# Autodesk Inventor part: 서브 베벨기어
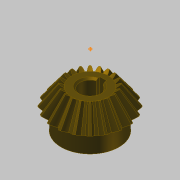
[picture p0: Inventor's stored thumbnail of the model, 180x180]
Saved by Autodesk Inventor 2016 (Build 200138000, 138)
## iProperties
Created: 2014-10
Part Number: 서브 베벨기어
Material: 강철, 탄소
Document SubType Name: Modeling
Designer: KYOUNG IL JANG
Categories: <?xml version="1.0" encoding="UTF-16"?> <MemberInstance><Categories><FamilyTemplate><FamilyTemplateParameter ValueType="xs:double" Id="1" ObjectReferenceKey="da
Mass: 135.037 g
Surface Area: 63.6518 cm^2
Volume: 17.1585 cm^3
Density: 7.87 g/cm^3
Appearance: 얼룩무늬
CustomPartVersion: 1
Revision Number: 1
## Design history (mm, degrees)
node "맨 위 점"
node "메쉬 평면2"
sketch "톱니 본체 스케치"
  geometry: L1 (0, 0)-(18.003, -31.331); L2 (18.003, -31.331)-(21.664, -28.891); L3 (21.664, -28.891)-(0, 0); L4 (20, -30)-(0, 0); L5 (10.813, -18.818)-(13.012, -17.352); L6 (18.003, -31.331)-(10.813, -18.818); L7 (21.664, -28.891)-(13.012, -17.352); L8 (0, -39.387)-(0, 6.564) reference; L9 (0, -30)-(21.664, -30)
  constraints: 16 end point, 4 point on line, 3 perpendicular, 2 collinear, 1 horizontal alignment, 1 vertical alignment
  dimensions: "d0" = 40 diameter of L4.start L8 (= da_de); "d1" = 36.00616 diameter of L1.end L8 (= da_dfe); "d2" = 43.3282 diameter of L2.end L8 (= da_dae); "d3" = 14.4 distance between parallel lines of L2 L5 (= da_b); "d4" = 28.8906 vertical distance of L2.end L1.start (= da_ve)
revolve "톱니 본체" sketch "톱니 본체 스케치" stored, may be unused: angle "d5" = 90 deg
node "시작점"
node "톱니 평면"
sketch "시작 스케치"
  geometry: L1 (0, -23.505)-(0, 10.645) reference; L2 (-0.834, -2.928)-(0.834, -2.928); A1 r 8.898 centre (-9.698, -3.713) between (-0.834, -2.928) and (-3.903, 3.04); A2 r 8.898 centre (9.698, -3.713) between (3.903, 3.04) and (0.834, -2.928); A3 r 27.357 centre (0, -24.037) between (3.903, 3.04) and (-3.903, 3.04); 1 further point
  constraints: 6 point on circle, 3 centre point, 3 symmetric about line, 2 end point, 1 coincident, 1 perpendicular, 1 other
  dimensions: "d7" = 8.89846 radius of A1 (= fd_rr); "d8" = 9.69794 horizontal distance of point (0, -24.037) A1.centre (= fd_x); "d9" = 20.32439 vertical distance of point (0, -24.037) A1.centre (= fd_y); "d57" = 27.35701 radius of A3 (= 0.5 x fd_dva + 0.3 x da_he); "d58" = 21.10901 distance from line of A3.centre L2 (= 0.5 x fd_dva - 1.12 x da_he)
node "끝점"
  node "끝 평면"
sketch "3D 스케치 오른쪽"
  node "Helical Curve Right" dims "d65" = 229.90621 (computed from da_dm, da_delta, da_beta), "d66" = 31.5, "d67" = 40 (= da_de), "d68" = -5.88003 (= -da_delta), "d69" = 12.16458 (computed from fd_loft, da_delta)
node "끝 평면 오른쪽"
sketch "끝 스케치 오른쪽"
  geometry: L1 (0, -22.649)-(0, 12.15) reference; L2 (-0.497, -1.72)-(0.497, -1.72); A1 r 5.299 centre (-5.775, -2.187) between (-0.497, -1.72) and (-2.324, 1.834); A2 r 5.299 centre (5.775, -2.187) between (2.324, 1.834) and (0.497, -1.72); A3 r 16.291 centre (0, -14.29) between (2.324, 1.834) and (-2.324, 1.834); 1 further point
  constraints: 6 point on circle, 3 centre point, 3 symmetric about line, 2 end point, 1 coincident, 1 perpendicular, 1 other
  dimensions: "d70" = 5.77526 horizontal distance of A3.centre A1.centre (computed from fd_x, fd_ratio); "d71" = 12.10346 vertical distance of point (0, -14.29) A1.centre (computed from fd_y, fd_ratio); "d72" = 5.29916 radius of A1 (computed from fd_rr, fd_ratio); "d73" = 12.57071 distance from line of point (0, -14.29) L2 (computed from d58, fd_ratio); "d74" = 16.29149 radius of A3 (computed from d57, fd_ratio)
feature "로프트 오른쪽" sketch "끝 스케치 오른쪽" dims "d75" = 0, "d77" = 0, "d79" = 0, "d80" = 90 deg, "d85" = 20, "d92" = 90 deg, "d93" = 90 deg, "da_teethtype" = 0 [user parameter]
sketch "3D 스케치 왼쪽"
  node "Helical Curve Left" dims "d26" = 229.90621 (computed from da_dm, da_delta, da_beta), "d27" = 12.16458 (computed from fd_loft, da_delta), "d28" = 40 (= da_de), "d29" = -5.88003 (= -da_delta)
node "끝 평면 왼쪽"
sketch "끝 스케치 왼쪽" dims "d56" = 10.82768 (derived)
  geometry: L1 (0, -35.087)-(0, 18.089) reference; L2 (-0.497, -1.716)-(0.497, -1.716); A1 r 5.299 centre (-5.775, -2.183) between (-0.497, -1.716) and (-2.324, 1.838); A2 r 5.299 centre (5.775, -2.183) between (2.324, 1.838) and (0.497, -1.716); A3 r 16.291 centre (0, -14.287) between (2.324, 1.838) and (-2.324, 1.838); 2 further points; 1 other entity
  constraints: 6 point on circle, 3 centre point, 3 symmetric about line, 2 end point, 1 coincident, 2 other
  dimensions: "d30" = 5.29916 radius of A1 (computed from fd_rr, fd_ratio); "d31" = 5.77526 horizontal distance of point (0, -14.287) A1.centre (computed from fd_x, fd_ratio); "d32" = 12.10346 vertical distance of A1.centre point (0, -14.287) (computed from fd_y, fd_ratio); "d61" = 16.29149 radius of A3 (computed from d57, fd_ratio); "d62" = 12.57071 distance from line of point (0, -14.287) L2 (computed from d58, fd_ratio)
feature "로프트 왼쪽" sketch "끝 스케치 왼쪽" dims "d35" = 0, "d37" = 0, "d39" = 0, "d40" = 90 deg, "d84" = 10, "d90" = 90 deg, "d91" = 90 deg, "da_teethtype" = 0 [user parameter]
sketch "본체 스케치"
  geometry: L1 (0, -35.038)-(0, -19.531) reference; L2 (18.003, -31.331)-(10.813, -18.818) reference; L3 (10.813, -18.818)-(0, -18.818); L4 (18.003, -31.331)-(0, -31.331)
  constraints: 4 end point, 2 perpendicular, 2 point on line
revolve "본체 고정" sketch "본체 스케치" stored, may be unused: angle "d46" = 90 deg
feature "피치 지름" dims angle "d47" = 90 deg
sketch "스케치8"
  geometry: C1 r 17 at (0, 0); 1 further point
  constraints: 1 centre point, 1 coincident
  dimensions: "d94" = 34 diameter of C1
extrude "돌출1" join sketch "스케치8" distance "d95" = 10; taper "d96" = 0 deg
sketch "스케치9"
  geometry: 1 further point
hole "구멍1" sketch "스케치9" at (0, 0) diameter "d97" = 12; stored, may be unused: countersink angle "d101" = 90 deg, drill point angle "d103" = 118 deg; dims "d98" = 6, "d99" = 4, "d100" = 2, "d102" = 8
sketch "스케치10"
  geometry: 1 further point
sketch "스케치11"
  geometry: 1 further point
sketch "스케치12"
  geometry: L1 (-2, 5.657)-(-2, 7.8); L2 (-2, 7.8)-(2, 7.8); L3 (2, 7.8)-(2, 5.657); A1 r 6 centre (0, 0) between (-2, 5.657) and (2, 5.657) reference; 1 further point
  constraints: 6 end point, 2 parallel, 2 point on circle, 1 perpendicular, 1 vertical
  dimensions: "d104" = 4 distance of L1.end L2.end; "d105" = 13.8 dimension on A1 L2
extrude "돌출2" cut sketch "스케치12" stored distance "d106" = 7; taper "d107" = 0 deg
chamfer "모따기1" distance "d108" = 1; stored, may be unused: second distance "d109" = 2, angle "d110" = 45 deg
body "Solid1"
feature "로프트" dims "d17" = 0, "d18" = 90 deg, "d19" = 0, "d20" = 90 deg, "d89" = 0, "da_teethtype" = 0 [user parameter]
pattern_circular "원형 패턴" dims angle "d22" = 360 deg, "d88" = 0, "da_teethtype" = 0 [user parameter]
pattern_circular "원형 패턴 오른쪽" dims angle "d82" = 360 deg, "da_teethtype" = 0 [user parameter]
pattern_circular "원형 패턴 왼쪽" dims angle "d42" = 360 deg, "da_teethtype" = 0 [user parameter]
sketch "끝 스케치"
  geometry: L1 (0, -15.359)-(0, 6.983) reference; L2 (-0.497, -1.72)-(0.497, -1.72); A1 r 5.299 centre (-5.775, -2.187) between (-0.497, -1.72) and (-2.324, 1.834); A2 r 5.299 centre (5.775, -2.187) between (2.324, 1.834) and (0.497, -1.72); A3 r 16.291 centre (0, -14.29) between (2.324, 1.834) and (-2.324, 1.834); 1 further point
  constraints: 6 point on circle, 3 centre point, 3 symmetric about line, 2 end point, 1 coincident, 1 other
  dimensions: "d12" = 5.29916 radius of A1 (computed from fd_rr, fd_ratio); "d15" = 5.77526 horizontal distance of A1.centre point (0, -14.29) (computed from fd_x, fd_ratio); "d16" = 12.10346 vertical distance of A1.centre point (0, -14.29) (computed from fd_y, fd_ratio); "d59" = 16.29149 radius of A3 (computed from d57, fd_ratio); "d60" = 12.57071 distance from line of A3.centre L2 (computed from d58, fd_ratio)
sketch "Sketch6"
  geometry: L1 (20, -30)-(0, 0) reference; L2 (0, -37.8)-(0, 6.3) reference
body "Srf1"
other parameters: "da_b" = 14.4 [user parameter; used in 2 equation terms], "da_de" = 40 [user parameter; used in 4 equation terms], "da_dae" = 43.3282 [user parameter; used in 2 equation terms], "da_dfe" = 36.00616 [user parameter; used in 1 equation term], "da_le" = 36.05551 [user parameter; used in 1 equation term], "da_omega" = 90 deg [user parameter; used in 1 equation term], "da_beta" = 0 [user parameter; used in 2 equation terms], "da_delta" = 5.88003 [user parameter; used in 8 equation terms], "da_alpha" = 20 deg [user parameter; used in 2 equation terms], "da_he" = 4.4 [user parameter; used in 4 equation terms], "da_ve" = 28.8906 [user parameter; used in 1 equation term], "fd_dv" = 48.07402 (computed from da_de, da_delta) [user parameter; used in 1 equation term], "fd_dva" = 52.07402 (computed from da_dae, da_delta) [user parameter; used in 3 equation terms], "fd_dvb" = 45.1748 (computed from fd_dv, da_alpha) [user parameter; used in 2 equation terms], "da_zv" = 240.37008 [user parameter; used in 1 equation term], "fd_loft" = 14.62 (= da_b + 0.05 x da_he) [user parameter; used in 4 equation terms], "fd_ratio" = 5.95514 (computed from da_le, fd_loft) [user parameter; used in 15 equation terms], "fd_rr" = 8.89846 (computed from fd_dd, fd_dvb) [user parameter; used in 6 equation terms], "fd_angle" = 0.66075 (computed from da_zv) [user parameter; used in 4 equation terms], "fd_x1" = 1.58709 (computed from da_dvw, fd_angle) [user parameter; used in 1 equation term], "fd_y1" = 23.98456 (computed from da_dvw, fd_angle) [user parameter; used in 1 equation term], "fd_x2" = 8.11084 (computed from fd_rr, fd_angle2, fd_angle) [user parameter; used in 1 equation term], "fd_y2" = 3.66016 (computed from fd_rr, fd_angle2, fd_angle) [user parameter; used in 1 equation term], "fd_x" = 9.69794 (= fd_x1 + fd_x2) [user parameter; used in 4 equation terms], "fd_y" = 20.32439 (= fd_y1 - fd_y2) [user parameter; used in 4 equation terms], "fd_angle2" = 3.57832 (computed from fd_dvb, fd_dd, da_alpha) [user parameter; used in 2 equation terms], "fd_dd" = 48.55402 (= fd_dva - 0.8 x da_he) [user parameter; used in 2 equation terms], "da_dvw" = 48.07402 [user parameter; used in 2 equation terms], "d11" = 14.62 (= fd_loft), "da_dm" = 32.01232 [user parameter; used in 2 equation terms], "da_x" = 0 [user parameter], "da_m" = 2 [user parameter], "d48" = 0, "d49" = 0, "d50" = 90 deg (= da_omega), "d51" = 9 deg (computed from da_z), "d52" = 0, "d53" = 0, "d54" = 0
